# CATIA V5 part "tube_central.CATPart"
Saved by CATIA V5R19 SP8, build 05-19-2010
Part number: tube_central
Bounding box of the stored display mesh (mm): x -420 to 420, y -20 to 1000, z -20 to 20
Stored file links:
  U:\Thinkmotion\Assemblage final\tube_central.CATPart
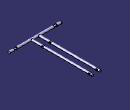
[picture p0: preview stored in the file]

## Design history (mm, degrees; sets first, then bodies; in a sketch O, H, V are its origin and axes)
Body1 (main body)
  Sketch1 on yz-plane, origin (0, 0, 0), H (0, 1, 0), V (0, 0, 1)
    circle A1 centre (0, 0) radius 20
    radius A1 = 20
  Pad1: profile Sketch1, direction (1, 0, 0), length 300
  Mirror1: of Pad1, Sketch1, about yz-plane
  Sketch2 on end face of Pad1, origin (300, 0, 0), H (0, 1, 0), V (0, 0, 1)
    circle A1 centre (0, 0) radius 10
    reference projected circle E1 centre (0, 0) radius 20 from edge [face of Mirror1 | end face of Pad1]
    radius A1 = 10
    concentricity: A1 E1
  Pad2: profile Sketch2, direction (1, 0, 0), length 50
  Mirror2: of Pad2, Sketch2, about yz-plane
  Sketch3 on end face of Pad2, origin (350, 0, 0), H (0, 1, 0), V (0, 0, 1)
    circle A1 centre (0, 0) radius 20
    reference projected circle E1 centre (0, 0) radius 20 from edge [face of Mirror1 | end face of Pad1]
    coincidence: E1 A1
  Pad3: profile Sketch3, direction (1, 0, 0), length 70
  Mirror3: of Pad3, Sketch3, about yz-plane
  Sketch4 on zx-plane, origin (0, 0, 0), H (-1, 0, 0), V (0, 0, 1)
    circle A1 centre (60, 0) radius 17.5
    point P1 (60, 0)
    reference intersected line E1 through (0, 0) direction (-1, 0) from xy-plane
    radius A1 = 17.5
    distance P1 V = 60
    coincidence: P1 E1
  Pad4: profile Sketch4, direction (0, 1, 0), length 1000
  Mirror4: of Pad4, Sketch4, about yz-plane
  Sketch5 on yz-plane, origin (0, 20.097, 4.2984), H (0, 1, 0), V (0, 0, 1)
    point P1 (939.903, -4.2984)
    reference intersected line E1 through (0, -4.2984) direction (-1, 0) from xy-plane
    reference intersected line E2 through (979.903, 0) direction (0, 1) from face of Mirror4
    distance P1 E2 = 40
    coincidence: P1 E1
  Hole1: placed by Sketch5, at (0, 960, 0) direction (-1, 0, 0), diameter 10, through (limit type 3)
  Mirror5: of Hole1, about yz-plane
  Sketch6 on yz-plane, origin (0, 12.1132, 18.156), H (0, 1, 0), V (0, 0, 1)
    point P1 (187.8868, -18.156)
    reference intersected line E1 through (0, -18.156) direction (-1, 0) from xy-plane
    reference intersected line E2 through (-12.1132, 0) direction (0, 1) from zx-plane
    distance P1 E2 = 200
    coincidence: P1 E1
  Hole2: placed by Sketch6, at (0, 200, 0) direction (-1, 0, 0), diameter 10, through (limit type 3)
  Mirror6: of Hole2, about yz-plane
  Sketch7 on xy-plane, origin (0, 0, 0), H (1, 0, 0), V (0, 1, 0)
    point P1 (100, 215)
    line L1 (100, 215) -> (70, 215)
    line L2 (70, 215) -> (70, 185)
    line L3 (70, 185) -> (100, 185)
    line L4 (100, 185) -> (100, 215)
    point P2 (70, 215)
    point P3 (70, 185)
    point P4 (100, 185)
    reference projected line E1 through (60, 0) direction (0, -1) from axis of face of Mirror4
    reference projected line E2 through (0, 200) direction (1, 0) from axis of face of Mirror6
    reference projected line E3 through (60, 0) direction (0, -1) from axis of face of Mirror4
    point P7 (20, 215)
    point P8 (50, 215)
    point P9 (50, 185)
    point P10 (20, 185)
    line L5 (20, 215) -> (50, 215)
    line L6 (50, 215) -> (50, 185)
    line L7 (50, 185) -> (20, 185)
    line L8 (20, 185) -> (20, 215)
    point P11 (-100, 215)
    point P12 (-70, 215)
    point P13 (-70, 185)
    point P14 (-100, 185)
    point P15 (-20, 215)
    point P16 (-50, 215)
    point P17 (-50, 185)
    point P18 (-20, 185)
    line L9 (-100, 215) -> (-70, 215)
    line L10 (-70, 215) -> (-70, 185)
    line L11 (-70, 185) -> (-100, 185)
    line L12 (-100, 185) -> (-100, 215)
    line L13 (-20, 215) -> (-50, 215)
    line L14 (-50, 215) -> (-50, 185)
    line L15 (-50, 185) -> (-20, 185)
    line L16 (-20, 185) -> (-20, 215)
    point P19 (110, 975)
    line L17 (110, 975) -> (70, 975)
    line L18 (70, 975) -> (70, 945)
    line L19 (70, 945) -> (110, 945)
    line L20 (110, 945) -> (110, 975)
    point P20 (70, 975)
    point P21 (70, 945)
    point P22 (110, 945)
    reference projected line E4 through (0, 960) direction (1, 0) from axis of face of Mirror5
    point P23 (10, 975)
    point P24 (50, 975)
    point P25 (50, 945)
    point P26 (10, 945)
    line L21 (10, 975) -> (50, 975)
    line L22 (50, 975) -> (50, 945)
    line L23 (50, 945) -> (10, 945)
    line L24 (10, 945) -> (10, 975)
    point P27 (-110, 975)
    point P28 (-70, 975)
    point P29 (-70, 945)
    point P30 (-110, 945)
    point P31 (-10, 975)
    point P32 (-50, 975)
    point P33 (-50, 945)
    point P34 (-10, 945)
    line L25 (-110, 975) -> (-70, 975)
    line L26 (-70, 975) -> (-70, 945)
    line L27 (-70, 945) -> (-110, 945)
    line L28 (-110, 945) -> (-110, 975)
    line L29 (-10, 975) -> (-50, 975)
    line L30 (-50, 975) -> (-50, 945)
    line L31 (-50, 945) -> (-10, 945)
    line L32 (-10, 945) -> (-10, 975)
    distance L2 E1 = 10
    length L4 = 30
    distance L1 E2 = 15
    length L20 = 30
    distance L17 E4 = 15
    distance L18 E3 = 10
    horizontal: L1 H, L3 H, L17 H, L19 H
    vertical: L2 V, L4 V, L18 V, L20 V
    symmetry: P1 P7 E3, P2 P8 E3, P3 P9 E3, P4 P10 E3, L1 L5 E3, L2 L6 E3, L3 L7 E3, L4 L8 E3, P1 P11 V, P2 P12 V, P3 P13 V, P4 P14 V, P7 P15 V, P8 P16 V, P9 P17 V, P10 P18 V, L1 L9 V, L2 L10 V, L3 L11 V, L4 L12 V, L5 L13 V, L6 L14 V, L7 L15 V, L8 L16 V, P19 P23 E3, P20 P24 E3, P21 P25 E3, P22 P26 E3, L17 L21 E3, L18 L22 E3, L19 L23 E3, L20 L24 E3, P19 P27 V, P20 P28 V, P21 P29 V, P22 P30 V, P23 P31 V, P24 P32 V, P25 P33 V, P26 P34 V, L17 L25 V, L18 L26 V, L19 L27 V, L20 L28 V, L21 L29 V, L22 L30 V, L23 L31 V, L24 L32 V
  Pocket1: profile Sketch7, direction (0, 0, -1), length 50, mirrored extent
